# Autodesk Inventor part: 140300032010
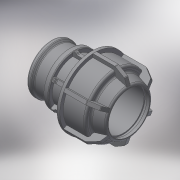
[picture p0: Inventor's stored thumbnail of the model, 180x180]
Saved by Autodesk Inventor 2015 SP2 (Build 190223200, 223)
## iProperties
Created: 2017-08
Part Number: 140300032010
Material: Generic
Description: PLASSON L.14 FEMALE ADAPTOR (SILVER) 32-1"
Document SubType Name: Modeling
Designer: KIM
Density: 1 g/cm^3
Appearance: Default
Author: KIM
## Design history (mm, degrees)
derived "140300.ipt"
feature "Solid1::140300.ipt"
tag "TaggingFeature1"
body "Solid1"
other parameters: "d1" = 32, "d2" = 61, "d4" = 15 deg, "d5" = 40.26, "d6" = 13.2858, "d9" = 30.291, "d10" = 61, "d11" = 39.3783, "d12" = 36.3492, "d13" = 42.4074, "d14" = 21, "d16" = 32.64, "d17" = 3.05, "d18" = 84, "d19" = 6.3, "d20" = 135 deg, "d21" = 6.3, "d22" = 36.3492, "d23" = 28.8, "d24" = 3.05, "d25" = 54.9, "d26" = 45.75, "d27" = 3.05, "d28" = 135 deg, "d29" = 1.83, "d31" = 1.6, "d44" = 0.64, "d45" = 0.96, "d46" = 150 deg, "d49" = 3.05, "d50" = 0, "d51" = 0.61, "d52" = 1.22, "d53" = 45 deg, "d55" = 7.692, "d56" = 3.05, "d57" = 0, "d58" = 0.96, "d61" = 360 deg, "d_" = 32, "G_" = 30.291, "E_" = 61, "H_" = 84, "l_" = 61, "l_2" = 21, "d54" = 19.23
